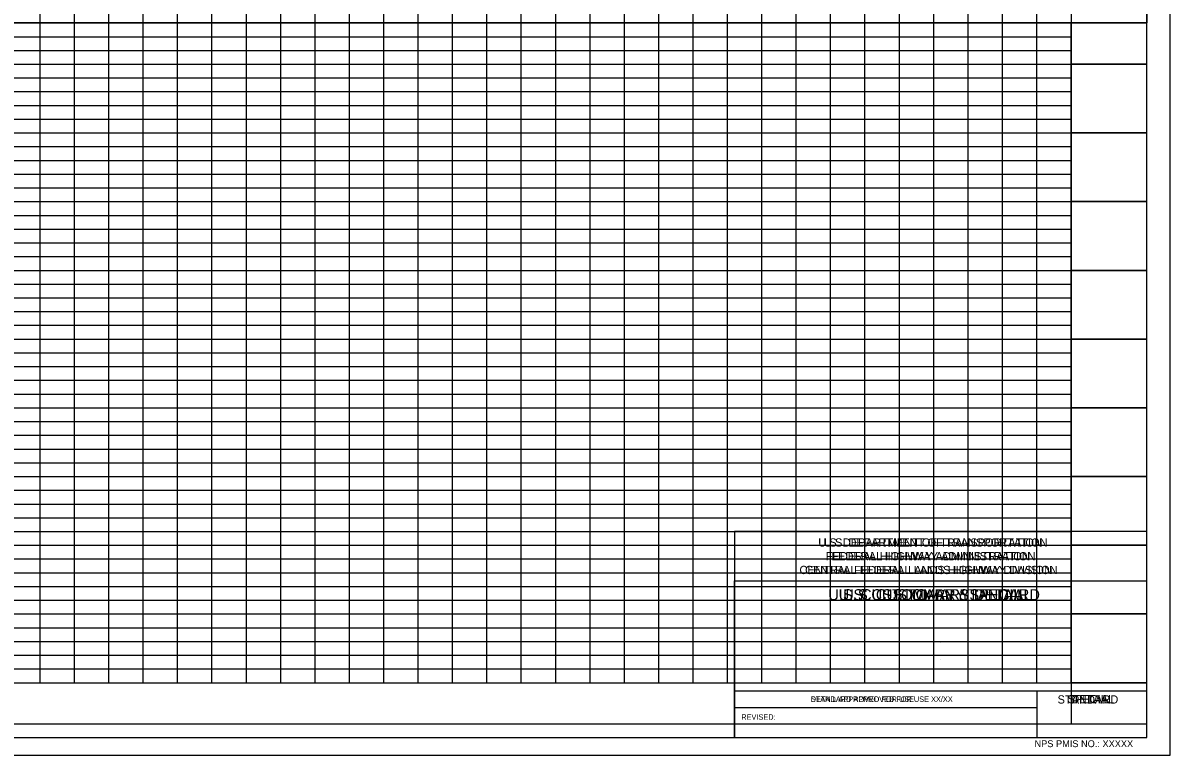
# Model space of a CAD drawing. Extents: x -87 to 2484, y -13 to 1056.
# Drawn here: x 742 to 1577, y -13 to 520 of the extents above; entities that cross this region are included whole.
import ezdxf

# ---------------------------------------------------------------- set-up
doc = ezdxf.new("R2010")
doc.units = 0
for name, color, linetype in [('D_CFL_Clip_Boundary_1', 7, 'Continuous'), ('D_CFL_Clip_Boundary_2', 7, 'Continuous'), ('D_CFL_Sheet_Border_ PlotShape', 7, 'Continuous'), ('D_CFL_Sheet_Border_Base', 7, 'Continuous'), ('D_CFL_Sheet_Border_Box', 7, 'Continuous'), ('D_CFL_Sheet_Border_Detail', 7, 'Continuous'), ('D_CFL_Sheet_Border_General', 7, 'Continuous'), ('D_CFL_Sheet_Border_NPS_Pkg', 7, 'Continuous'), ('D_CFL_Sheet_Border_Plan_Plan', 7, 'Continuous'), ('D_CFL_Sheet_Border_PnP', 7, 'Continuous'), ('D_CFL_Sheet_Border_Profile', 7, 'Continuous'), ('D_CFL_Sheet_Border_Special', 7, 'Continuous'), ('D_CFL_Sheet_Border_Standard', 7, 'Continuous')]:
    doc.layers.add(name, color=color, linetype=linetype)

msp = doc.modelspace()

# ---------------------------------------------------------------- linework, layer by layer
at = {"layer": 'D_CFL_Clip_Boundary_1'}
msp.add_lwpolyline([(0, 520), (0, 1040), (1305, 1040), (1305, 1000), (1560, 1000), (1560, 520)], close=True, dxfattribs=at)
msp.add_lwpolyline([(0, 520), (0, 1040), (1305, 1040), (1305, 1000), (1560, 1000), (1560, 520)], close=True, dxfattribs=at)
at = {"layer": 'D_CFL_Clip_Boundary_2'}
msp.add_lwpolyline([(1505, 520), (55, 520), (55, 40), (1505, 40)], close=True, dxfattribs=at)
msp.add_lwpolyline([(1505, 520), (55, 520), (55, 40), (1505, 40)], close=True, dxfattribs=at)
at = {"layer": 'D_CFL_Sheet_Border_ PlotShape'}
msp.add_lwpolyline([(-86.9, -12.66), (1576.9, -12.66), (1576.9, 1052.65), (-86.9, 1052.65)], close=True, dxfattribs=at)
at = {"layer": 'D_CFL_Sheet_Border_Base'}
msp.add_lwpolyline([(0, 0), (1560, 0), (1560, 1040), (0, 1040)], close=True, dxfattribs=at)
msp.add_lwpolyline([(0, 0), (1560, 0), (1560, 1040), (0, 1040)], close=True, dxfattribs=at)
at = {"layer": 'D_CFL_Sheet_Border_Box'}
for p, q in [((1260, 0), (1260, 114)), ((1260, 114), (1560.01, 114)), ((1260, 0), (1260, 114)), ((1260, 114), (1560.01, 114)), ((1410.01, 57), (1410.01, 57)), ((1410.01, 57), (1410.01, 57))]:
    msp.add_line(p, q, dxfattribs=at)
at = {"layer": 'D_CFL_Sheet_Border_Detail'}
for p, q in [((1260, 114), (1560.01, 114)), ((1260, 114), (1560.01, 114)), ((1410.01, 69), (1410.01, 69)), ((1410.01, 69), (1410.01, 69)), ((1260, 34), (1560.01, 34)), ((1260, 34), (1560.01, 34)), ((1480.01, 34), (1480.01, 0)), ((1480.01, 34), (1480.01, 0)), ((1260, 22), (1480.01, 22)), ((1260, 22), (1480.01, 22))]:
    msp.add_line(p, q, dxfattribs=at)
msp.add_lwpolyline([(1560.01, 150), (1260, 150), (1260, 0)], dxfattribs=at)
msp.add_lwpolyline([(1560.01, 150), (1260, 150), (1260, 0)], dxfattribs=at)
at = {"layer": 'D_CFL_Sheet_Border_General'}
for p, q in [((1260, 114), (1560.01, 114)), ((1260, 114), (1560.01, 114)), ((1410.01, 57), (1410.01, 57)), ((1410.01, 57), (1410.01, 57))]:
    msp.add_line(p, q, dxfattribs=at)
msp.add_lwpolyline([(1560.01, 150), (1260, 150), (1260, 0)], dxfattribs=at)
msp.add_lwpolyline([(1560.01, 150), (1260, 150), (1260, 0)], dxfattribs=at)
at = {"layer": 'D_CFL_Sheet_Border_Plan_Plan'}
for p, q in [((1260, 0), (1260, 114)), ((1260, 114), (1560.01, 114)), ((1260, 0), (1260, 114)), ((1260, 114), (1560.01, 114)), ((1410.01, 57), (1410.01, 57)), ((1410.01, 57), (1410.01, 57))]:
    msp.add_line(p, q, dxfattribs=at)
at = {"layer": 'D_CFL_Sheet_Border_PnP'}
for p, q in [((0, 520), (1560, 520)), ((0, 520), (1560, 520)), ((755, 40), (755, 520)), ((755, 40), (755, 520)), ((780, 40), (780, 520)), ((780, 40), (780, 520)), ((805, 40), (805, 520)), ((805, 40), (805, 520)), ((830, 40), (830, 520)), ((830, 40), (830, 520)), ((855, 40), (855, 520)), ((855, 40), (855, 520)), ((880, 40), (880, 520)), ((880, 40), (880, 520)), ((905, 40), (905, 520)), ((905, 40), (905, 520)), ((930, 40), (930, 520)), ((930, 40), (930, 520)), ((955, 40), (955, 520)), ((955, 40), (955, 520)), ((980, 40), (980, 520)), ((980, 40), (980, 520)), ((1005, 40), (1005, 520)), ((1005, 40), (1005, 520)), ((1030, 40), (1030, 520)), ((1030, 40), (1030, 520)), ((1055, 40), (1055, 520)), ((1055, 40), (1055, 520)), ((1080, 40), (1080, 520)), ((1080, 40), (1080, 520)), ((1105, 40), (1105, 520)), ((1105, 40), (1105, 520)), ((1130, 40), (1130, 520)), ((1130, 40), (1130, 520)), ((1155, 40), (1155, 520)), ((1155, 40), (1155, 520)), ((1180, 40), (1180, 520)), ((1180, 40), (1180, 520)), ((1205, 40), (1205, 520)), ((1205, 40), (1205, 520)), ((1230, 40), (1230, 520)), ((1230, 40), (1230, 520)), ((1255, 40), (1255, 520)), ((1255, 40), (1255, 520)), ((1280, 40), (1280, 520)), ((1280, 40), (1280, 520)), ((1305, 40), (1305, 520)), ((1305, 40), (1305, 520)), ((1330, 40), (1330, 520)), ((1330, 40), (1330, 520)), ((1355, 40), (1355, 520)), ((1355, 40), (1355, 520)), ((1380, 40), (1380, 520)), ((1380, 40), (1380, 520)), ((1405, 40), (1405, 520)), ((1405, 40), (1405, 520)), ((1430, 40), (1430, 520)), ((1430, 40), (1430, 520)), ((1455, 40), (1455, 520)), ((1455, 40), (1455, 520)), ((1480, 40), (1480, 520)), ((1480, 40), (1480, 520)), ((1505, 520), (1505, 10)), ((1505, 520), (1505, 10)), ((55, 510), (1505, 510)), ((55, 510), (1505, 510)), ((55, 500), (1505, 500)), ((55, 500), (1505, 500)), ((55, 490), (1505, 490)), ((55, 490), (1505, 490)), ((1505, 490), (1560, 490)), ((1505, 490), (1560, 490)), ((55, 480), (1505, 480)), ((55, 480), (1505, 480)), ((55, 470), (1505, 470)), ((55, 470), (1505, 470)), ((55, 460), (1505, 460)), ((55, 460), (1505, 460)), ((55, 450), (1505, 450)), ((55, 450), (1505, 450)), ((55, 440), (1505, 440)), ((55, 440), (1505, 440)), ((1505, 440), (1560, 440)), ((1505, 440), (1560, 440)), ((55, 430), (1505, 430)), ((55, 430), (1505, 430)), ((55, 420), (1505, 420)), ((55, 420), (1505, 420)), ((55, 410), (1505, 410)), ((55, 410), (1505, 410)), ((55, 400), (1505, 400)), ((55, 400), (1505, 400)), ((55, 390), (1505, 390)), ((55, 390), (1505, 390)), ((1505, 390), (1560, 390)), ((1505, 390), (1560, 390)), ((55, 380), (1505, 380)), ((55, 380), (1505, 380)), ((55, 370), (1505, 370)), ((55, 370), (1505, 370)), ((55, 360), (1505, 360)), ((55, 360), (1505, 360)), ((55, 350), (1505, 350)), ((55, 350), (1505, 350)), ((55, 340), (1505, 340)), ((55, 340), (1505, 340)), ((1505, 340), (1560, 340)), ((1505, 340), (1560, 340)), ((55, 330), (1505, 330)), ((55, 330), (1505, 330)), ((55, 320), (1505, 320)), ((55, 320), (1505, 320)), ((55, 310), (1505, 310)), ((55, 310), (1505, 310)), ((55, 300), (1505, 300)), ((55, 300), (1505, 300)), ((55, 290), (1505, 290)), ((55, 290), (1505, 290)), ((1505, 290), (1560, 290)), ((1505, 290), (1560, 290)), ((55, 280), (1505, 280)), ((55, 280), (1505, 280)), ((55, 270), (1505, 270)), ((55, 270), (1505, 270)), ((55, 260), (1505, 260)), ((55, 260), (1505, 260)), ((55, 250), (1505, 250)), ((55, 250), (1505, 250)), ((55, 240), (1505, 240)), ((55, 240), (1505, 240)), ((1505, 240), (1560, 240)), ((1505, 240), (1560, 240)), ((55, 230), (1505, 230)), ((55, 230), (1505, 230)), ((55, 220), (1505, 220)), ((55, 220), (1505, 220)), ((55, 210), (1505, 210)), ((55, 210), (1505, 210)), ((55, 200), (1505, 200)), ((55, 200), (1505, 200)), ((55, 190), (1505, 190)), ((55, 190), (1505, 190)), ((1505, 190), (1560, 190)), ((1505, 190), (1560, 190)), ((55, 180), (1505, 180)), ((55, 180), (1505, 180)), ((55, 170), (1505, 170)), ((55, 170), (1505, 170)), ((55, 160), (1505, 160)), ((55, 160), (1505, 160)), ((55, 150), (1505, 150)), ((55, 150), (1505, 150)), ((55, 140), (1505, 140)), ((55, 140), (1505, 140)), ((1505, 140), (1560, 140)), ((1505, 140), (1560, 140)), ((55, 130), (1505, 130)), ((55, 130), (1505, 130)), ((55, 120), (1505, 120)), ((55, 120), (1505, 120)), ((55, 110), (1505, 110)), ((55, 110), (1505, 110)), ((55, 100), (1505, 100)), ((55, 100), (1505, 100)), ((55, 90), (1505, 90)), ((55, 90), (1505, 90)), ((1505, 90), (1560, 90)), ((1505, 90), (1560, 90)), ((55, 80), (1505, 80)), ((55, 80), (1505, 80)), ((55, 70), (1505, 70)), ((55, 70), (1505, 70)), ((55, 60), (1505, 60)), ((55, 60), (1505, 60)), ((55, 50), (1505, 50)), ((55, 50), (1505, 50)), ((55, 40), (1505, 40)), ((55, 40), (1505, 40)), ((1505, 40), (1560, 40)), ((1505, 40), (1560, 40)), ((0, 10), (1560, 10)), ((0, 10), (1560, 10))]:
    msp.add_line(p, q, dxfattribs=at)
at = {"layer": 'D_CFL_Sheet_Border_Profile'}
for p, q in [((755, 40), (755, 990)), ((755, 40), (755, 990)), ((780, 40), (780, 990)), ((780, 40), (780, 990)), ((805, 40), (805, 990)), ((805, 40), (805, 990)), ((830, 40), (830, 990)), ((830, 40), (830, 990)), ((855, 40), (855, 990)), ((855, 40), (855, 990)), ((880, 40), (880, 990)), ((880, 40), (880, 990)), ((905, 40), (905, 990)), ((905, 40), (905, 990)), ((930, 40), (930, 990)), ((930, 40), (930, 990)), ((955, 40), (955, 990)), ((955, 40), (955, 990)), ((980, 40), (980, 990)), ((980, 40), (980, 990)), ((1005, 40), (1005, 990)), ((1005, 40), (1005, 990)), ((1030, 40), (1030, 990)), ((1030, 40), (1030, 990)), ((1055, 40), (1055, 990)), ((1055, 40), (1055, 990)), ((1080, 40), (1080, 990)), ((1080, 40), (1080, 990)), ((1105, 40), (1105, 990)), ((1105, 40), (1105, 990)), ((1130, 40), (1130, 990)), ((1130, 40), (1130, 990)), ((1155, 40), (1155, 990)), ((1155, 40), (1155, 990)), ((1180, 40), (1180, 990)), ((1180, 40), (1180, 990)), ((1205, 40), (1205, 990)), ((1205, 40), (1205, 990)), ((1230, 40), (1230, 990)), ((1230, 40), (1230, 990)), ((1255, 40), (1255, 990)), ((1255, 40), (1255, 990)), ((1280, 40), (1280, 990)), ((1280, 40), (1280, 990)), ((1305, 40), (1305, 990)), ((1305, 40), (1305, 990)), ((1330, 40), (1330, 990)), ((1330, 40), (1330, 990)), ((1355, 40), (1355, 990)), ((1355, 40), (1355, 990)), ((1380, 40), (1380, 990)), ((1380, 40), (1380, 990)), ((1405, 40), (1405, 990)), ((1405, 40), (1405, 990)), ((1430, 40), (1430, 990)), ((1430, 40), (1430, 990)), ((1455, 40), (1455, 990)), ((1455, 40), (1455, 990)), ((1480, 40), (1480, 990)), ((1480, 40), (1480, 990)), ((1505, 990), (1505, 10)), ((1505, 990), (1505, 10)), ((55, 520), (1505, 520)), ((55, 520), (1505, 520)), ((55, 510), (1505, 510)), ((55, 510), (1505, 510)), ((55, 500), (1505, 500)), ((55, 500), (1505, 500)), ((55, 490), (1505, 490)), ((55, 490), (1505, 490)), ((1560, 490), (1505, 490)), ((1560, 490), (1505, 490)), ((55, 480), (1505, 480)), ((55, 480), (1505, 480)), ((55, 470), (1505, 470)), ((55, 470), (1505, 470)), ((55, 460), (1505, 460)), ((55, 460), (1505, 460)), ((55, 450), (1505, 450)), ((55, 450), (1505, 450)), ((55, 440), (1505, 440)), ((55, 440), (1505, 440)), ((1560, 440), (1505, 440)), ((1560, 440), (1505, 440)), ((55, 430), (1505, 430)), ((55, 430), (1505, 430)), ((55, 420), (1505, 420)), ((55, 420), (1505, 420)), ((55, 410), (1505, 410)), ((55, 410), (1505, 410)), ((55, 400), (1505, 400)), ((55, 400), (1505, 400)), ((55, 390), (1505, 390)), ((55, 390), (1505, 390)), ((1560, 390), (1505, 390)), ((1560, 390), (1505, 390)), ((55, 380), (1505, 380)), ((55, 380), (1505, 380)), ((55, 370), (1505, 370)), ((55, 370), (1505, 370)), ((55, 360), (1505, 360)), ((55, 360), (1505, 360)), ((55, 350), (1505, 350)), ((55, 350), (1505, 350)), ((55, 340), (1505, 340)), ((55, 340), (1505, 340)), ((1560, 340), (1505, 340)), ((1560, 340), (1505, 340)), ((55, 330), (1505, 330)), ((55, 330), (1505, 330)), ((55, 320), (1505, 320)), ((55, 320), (1505, 320)), ((55, 310), (1505, 310)), ((55, 310), (1505, 310)), ((55, 300), (1505, 300)), ((55, 300), (1505, 300)), ((55, 290), (1505, 290)), ((55, 290), (1505, 290)), ((1560, 290), (1505, 290)), ((1560, 290), (1505, 290)), ((55, 280), (1505, 280)), ((55, 280), (1505, 280)), ((55, 270), (1505, 270)), ((55, 270), (1505, 270)), ((55, 260), (1505, 260)), ((55, 260), (1505, 260)), ((55, 250), (1505, 250)), ((55, 250), (1505, 250)), ((55, 240), (1505, 240)), ((55, 240), (1505, 240)), ((1560, 240), (1505, 240)), ((1560, 240), (1505, 240)), ((55, 230), (1505, 230)), ((55, 230), (1505, 230)), ((55, 220), (1505, 220)), ((55, 220), (1505, 220)), ((55, 210), (1505, 210)), ((55, 210), (1505, 210)), ((55, 200), (1505, 200)), ((55, 200), (1505, 200)), ((55, 190), (1505, 190)), ((55, 190), (1505, 190)), ((1560, 190), (1505, 190)), ((1560, 190), (1505, 190)), ((55, 180), (1505, 180)), ((55, 180), (1505, 180)), ((55, 170), (1505, 170)), ((55, 170), (1505, 170)), ((55, 160), (1505, 160)), ((55, 160), (1505, 160)), ((55, 150), (1505, 150)), ((55, 150), (1505, 150)), ((55, 140), (1505, 140)), ((55, 140), (1505, 140)), ((1560, 140), (1505, 140)), ((1560, 140), (1505, 140)), ((55, 130), (1505, 130)), ((55, 130), (1505, 130)), ((55, 120), (1505, 120)), ((55, 120), (1505, 120)), ((55, 110), (1505, 110)), ((55, 110), (1505, 110)), ((55, 100), (1505, 100)), ((55, 100), (1505, 100)), ((55, 90), (1505, 90)), ((55, 90), (1505, 90)), ((1560, 90), (1505, 90)), ((1560, 90), (1505, 90)), ((55, 80), (1505, 80)), ((55, 80), (1505, 80)), ((55, 70), (1505, 70)), ((55, 70), (1505, 70)), ((55, 60), (1505, 60)), ((55, 60), (1505, 60)), ((55, 50), (1505, 50)), ((55, 50), (1505, 50)), ((55, 40), (1505, 40)), ((55, 40), (1505, 40)), ((1560, 40), (1505, 40)), ((1560, 40), (1505, 40)), ((0, 10), (1560, 10)), ((0, 10), (1560, 10))]:
    msp.add_line(p, q, dxfattribs=at)
at = {"layer": 'D_CFL_Sheet_Border_Special'}
for p, q in [((1260, 114), (1560.01, 114)), ((1260, 114), (1560.01, 114)), ((1410.01, 69), (1410.01, 69)), ((1410.01, 69), (1410.01, 69)), ((1260, 34), (1560.01, 34)), ((1260, 34), (1560.01, 34)), ((1480.01, 34), (1480.01, 0)), ((1480.01, 34), (1480.01, 0)), ((1260, 22), (1480.01, 22)), ((1260, 22), (1480.01, 22))]:
    msp.add_line(p, q, dxfattribs=at)
msp.add_lwpolyline([(1560.01, 150), (1260, 150), (1260, 0)], dxfattribs=at)
msp.add_lwpolyline([(1560.01, 150), (1260, 150), (1260, 0)], dxfattribs=at)
at = {"layer": 'D_CFL_Sheet_Border_Standard'}
for p, q in [((1260, 114), (1560.01, 114)), ((1260, 114), (1560.01, 114)), ((1410.01, 69), (1410.01, 69)), ((1410.01, 69), (1410.01, 69)), ((1260, 34), (1560.01, 34)), ((1260, 34), (1560.01, 34)), ((1480.01, 34), (1480.01, 0)), ((1480.01, 34), (1480.01, 0)), ((1260, 22), (1480.01, 22)), ((1260, 22), (1480.01, 22))]:
    msp.add_line(p, q, dxfattribs=at)
msp.add_lwpolyline([(1560.01, 150), (1260, 150), (1260, 0)], dxfattribs=at)
msp.add_lwpolyline([(1560.01, 150), (1260, 150), (1260, 0)], dxfattribs=at)

# ---------------------------------------------------------------- texts
at = {"layer": 'D_CFL_Sheet_Border_Detail'}
for s, height, p in [('U.S. DEPARTMENT OF TRANSPORTATION', 6, (1321.03, 139)), ('U.S. DEPARTMENT OF TRANSPORTATION', 6, (1321.03, 139)), ('FEDERAL HIGHWAY ADMINISTRATION', 6, (1326.45, 129)), ('FEDERAL HIGHWAY ADMINISTRATION', 6, (1326.45, 129)), ('CENTRAL FEDERAL LANDS HIGHWAY DIVISION', 6, (1307.33, 119)), ('CENTRAL FEDERAL LANDS HIGHWAY DIVISION', 6, (1307.33, 119)), ('U.S. CUSTOMARY DETAIL', 8, (1339.14, 100)), ('U.S. CUSTOMARY DETAIL', 8, (1339.14, 100)), ('DETAIL APPROVED FOR USE', 4, (1315.5, 26)), ('DETAIL APPROVED FOR USE', 4, (1315.5, 26)), ('DETAIL', 6, (1505.07, 25)), ('DETAIL', 6, (1505.07, 25)), ('REVISED:                                                 ', 4, (1265, 13)), ('REVISED:                                                 ', 4, (1265, 13))]:
    msp.add_text(s, height=height, dxfattribs=at).set_placement(p)
at = {"layer": 'D_CFL_Sheet_Border_General'}
for s, p in [('U.S. DEPARTMENT OF TRANSPORTATION', (1325.16, 139)), ('U.S. DEPARTMENT OF TRANSPORTATION', (1325.16, 139)), ('FEDERAL HIGHWAY ADMINISTRATION', (1330.57, 129)), ('FEDERAL HIGHWAY ADMINISTRATION', (1330.57, 129)), ('CENTRAL FEDERAL LANDS HIGHWAY DIVISION', (1311.46, 119)), ('CENTRAL FEDERAL LANDS HIGHWAY DIVISION', (1311.46, 119))]:
    msp.add_text(s, height=6, dxfattribs=at).set_placement(p)
at = {"layer": 'D_CFL_Sheet_Border_NPS_Pkg'}
msp.add_text('NPS PMIS NO.: XXXXX ', height=5, dxfattribs=at).set_placement((1478.34, -6.9))
msp.add_text('NPS PMIS NO.: XXXXX ', height=5, dxfattribs=at).set_placement((1478.34, -6.9))
at = {"layer": 'D_CFL_Sheet_Border_Special'}
for s, height, p in [('U.S. DEPARTMENT OF TRANSPORTATION', 6, (1325.16, 139)), ('U.S. DEPARTMENT OF TRANSPORTATION', 6, (1325.16, 139)), ('FEDERAL HIGHWAY ADMINISTRATION', 6, (1330.57, 129)), ('FEDERAL HIGHWAY ADMINISTRATION', 6, (1330.57, 129)), ('CENTRAL FEDERAL LANDS HIGHWAY DIVISION', 6, (1311.46, 119)), ('CENTRAL FEDERAL LANDS HIGHWAY DIVISION', 6, (1311.46, 119)), ('U.S. CUSTOMARY SPECIAL', 8, (1335.85, 100)), ('U.S. CUSTOMARY SPECIAL', 8, (1335.85, 100)), ('SPECIAL', 6, (1502.35, 25)), ('SPECIAL', 6, (1502.35, 25))]:
    msp.add_text(s, height=height, dxfattribs=at).set_placement(p)
at = {"layer": 'D_CFL_Sheet_Border_Standard'}
for s, height, p in [('U.S. DEPARTMENT OF TRANSPORTATION', 6, (1325.16, 139)), ('U.S. DEPARTMENT OF TRANSPORTATION', 6, (1325.16, 139)), ('FEDERAL HIGHWAY ADMINISTRATION', 6, (1330.57, 129)), ('FEDERAL HIGHWAY ADMINISTRATION', 6, (1330.57, 129)), ('FEDERAL LANDS HIGHWAY OFFICE', 6, (1337.17, 119)), ('FEDERAL LANDS HIGHWAY OFFICE', 6, (1337.17, 119)), ('U.S. CUSTOMARY STANDARD', 8, (1328.3, 100)), ('U.S. CUSTOMARY STANDARD', 8, (1328.3, 100)), ('STANDARD APPROVED FOR USE XX/XX', 4, (1315.67, 26)), ('STANDARD APPROVED FOR USE XX/XX', 4, (1315.67, 26)), ('STANDARD', 6, (1495.09, 24.79)), ('STANDARD', 6, (1495.09, 24.79)), ('REVISED:                                                 ', 4, (1265, 13)), ('REVISED:                                                 ', 4, (1265, 13))]:
    msp.add_text(s, height=height, dxfattribs=at).set_placement(p)

doc.saveas('drawing.dxf')
